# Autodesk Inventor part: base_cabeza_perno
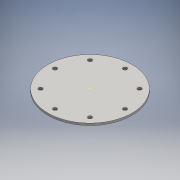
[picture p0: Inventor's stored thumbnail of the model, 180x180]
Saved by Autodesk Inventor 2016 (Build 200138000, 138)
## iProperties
Created: 2016-06
Part Number: base_cabeza_perno
Material: Genérico
Document SubType Name: Modeling
Designer: adm
Density: 1 g/cm^3
Appearance: Valor por defecto
Author: adm
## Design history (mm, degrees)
sketch "Boceto1"
  geometry: C1 r 60 at (0, 0); 1 further point
  constraints: 1 centre point, 1 coincident
  dimensions: "d0" = 120 diameter of C1
extrude "Extrusión1" new body sketch "Boceto1" distance "d1" = 3; taper "d2" = 0 deg
sketch "Boceto2"
  geometry: C1 r 1.5 at (0, 50); C2 r 1.5 at (-35.355, 35.355); C3 r 1.5 at (35.355, 35.355); C4 r 1.5 at (0, -50); C5 r 1.985 at (-35.355, -35.355); C6 r 1.796 at (35.355, -35.355); 1 further point
  constraints: 6 centre point
  dimensions: "d3" = 50 distance of point (0, 0) C1.centre; "d4" = 3 diameter of C1; "d5" = 3 diameter of C2; "d6" = 35.35534 horizontal distance of point (0, 0) C2.centre; "d7" = 35.35534 horizontal distance of point (0, 0) C2.centre; "d8" = 3 diameter of C3; "d9" = 35.35534 horizontal distance of point (0, 0) C3.centre; "d10" = 35.35534 horizontal distance of point (0, 0) C3.centre; "d11" = 3 diameter of C4; "d12" = 50 distance of point (0, 0) C4.centre; "d13" = 35.35534 horizontal distance of point (0, 0) C6.centre; "d14" = 35.35534 horizontal distance of point (0, 0) C5.centre
hole "Agujero1" sketch "Boceto2" at (-35.355, 35.355), (0, 50), (35.355, 35.355), (35.355, -35.355), (0, -50), (-35.355, -35.355) diameter "d15" = 5.5; stored, may be unused: countersink angle "d19" = 90 deg, drill point angle "d21" = 118 deg; dims "d16" = 6, "d17" = 4, "d18" = 2, "d20" = 8
sketch "Boceto3"
  geometry: 1 further point
sketch "Boceto4"
  geometry: C1 r 1.5 at (-50, 0); C2 r 1.5 at (50, 0); 1 further point
  constraints: 2 centre point
  dimensions: "d22" = 3 diameter of C1; "d23" = 3 diameter of C2; "d24" = 50 distance of C2.centre point (0, 0); "d25" = 50 distance of point (0, 0) C1.centre
hole "Agujero2" sketch "Boceto4" at (-50, 0), (50, 0) diameter "d26" = 5.5; stored, may be unused: countersink angle "d30" = 90 deg, drill point angle "d32" = 118 deg; dims "d27" = 6, "d28" = 4, "d29" = 2, "d31" = 8
sketch "Boceto5"
  geometry: 1 further point
node "Sólido1"
